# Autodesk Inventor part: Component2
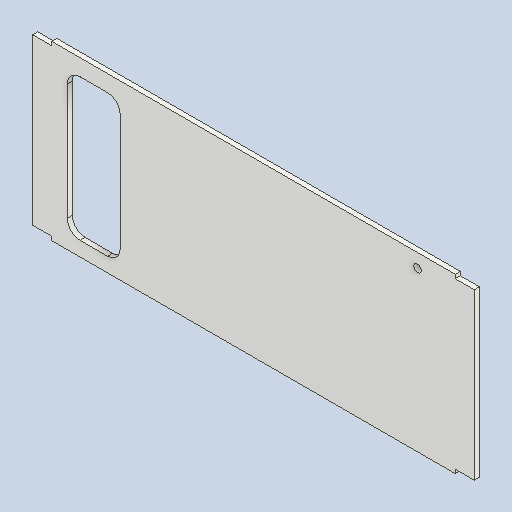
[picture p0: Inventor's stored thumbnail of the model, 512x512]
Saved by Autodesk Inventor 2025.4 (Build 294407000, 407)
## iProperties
Created: 2026-06
Part Number: Component2
Material: Generic
Document SubType Name: Modeling
Designer: AdminForWorker
Density: 1 g/cm^3
Appearance: Default
Title: Component2
Author: AdminForWorker
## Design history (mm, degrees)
feature "Body1"
body "Solid1"
